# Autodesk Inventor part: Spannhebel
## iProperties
Company: HERDT-Verlag
Created: 2006-01
Part Number: Spannhebel
Material: Messing 340(poliert)
Document SubType Name: Modeling
Designer: Eichenseer
Project: Inventor 11 - Grundkurs
Checked By: G. Lehmann
Engr Approved By: M. Grouls
Description: DIN 1017 70x8x165
Engineer: Käs
Title: Spannhebel
Author: P. Tropf
Subject: Inventor 10 - Grundkurs
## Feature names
1. Extrusion2
2. Fase1 [Chamfer]
3. Rundung1 [Fillet]
